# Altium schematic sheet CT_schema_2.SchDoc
size 362 x 192 mm
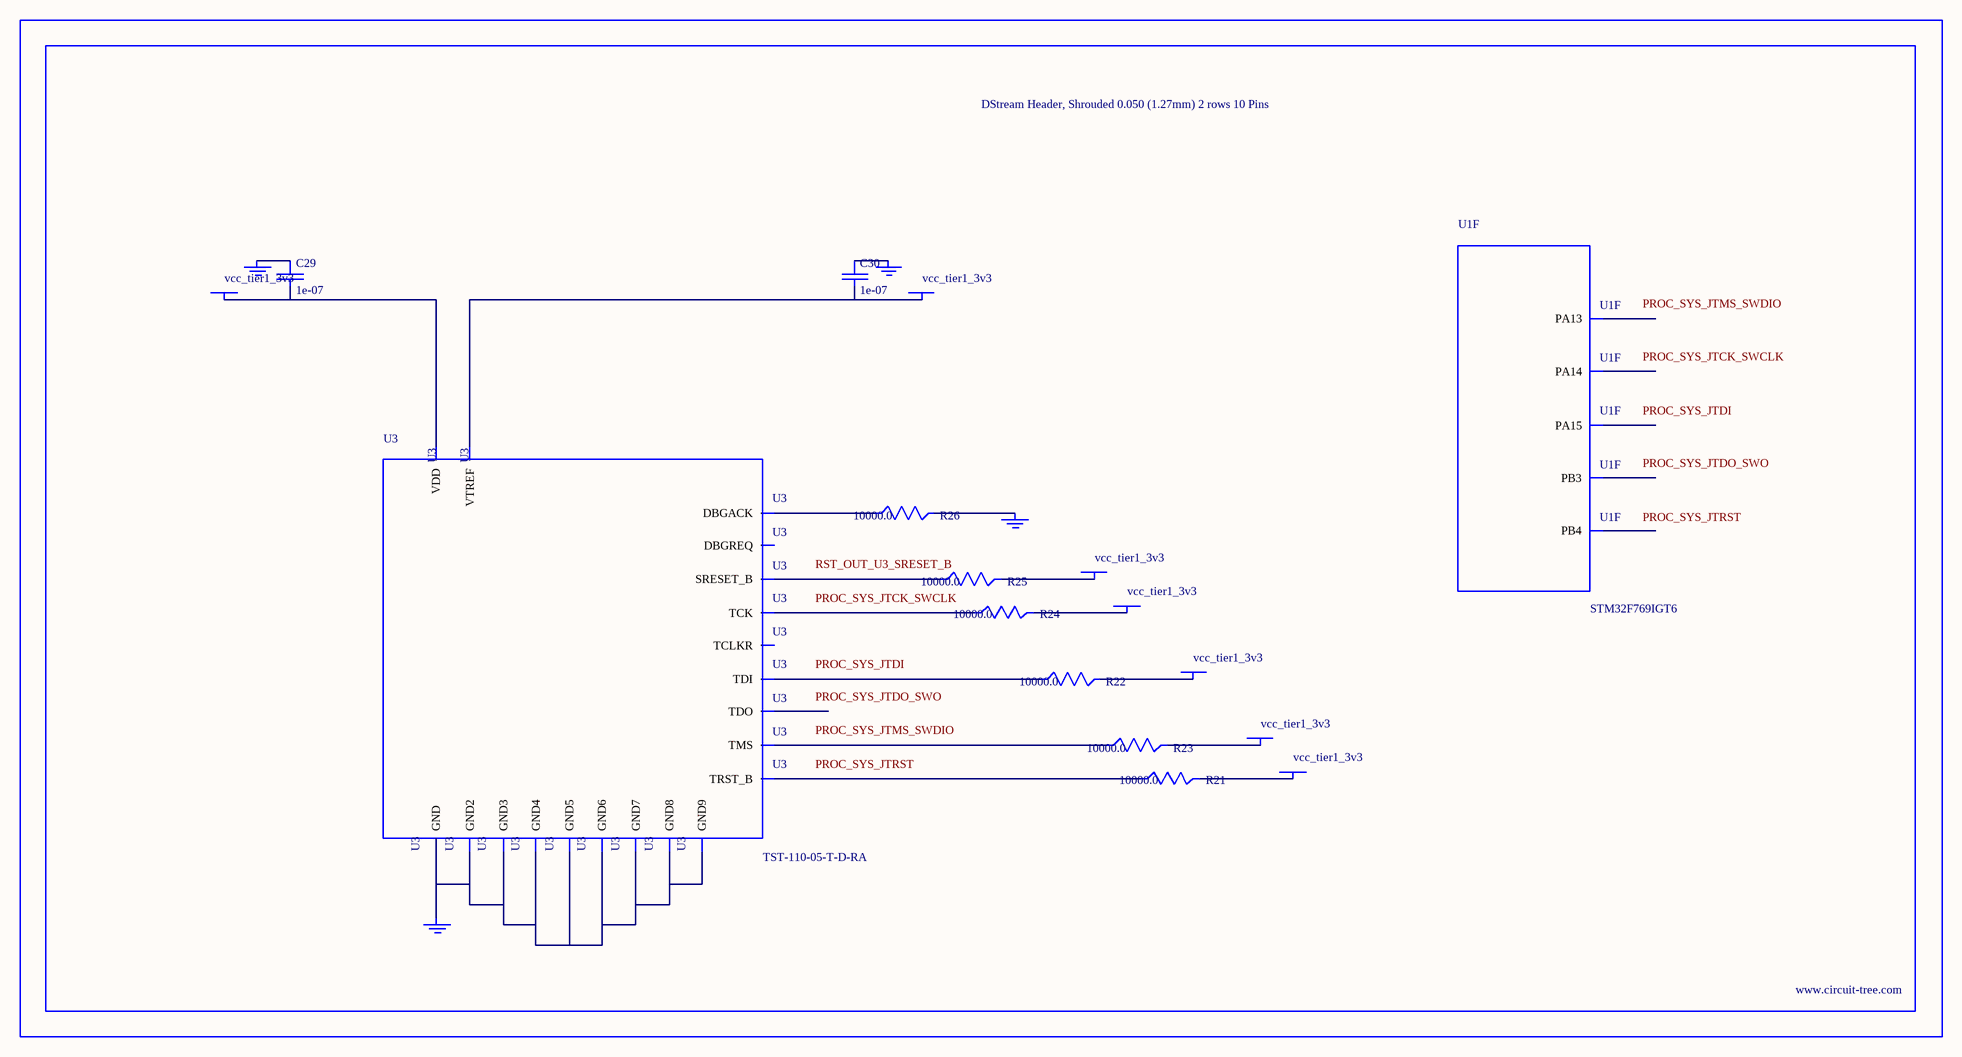
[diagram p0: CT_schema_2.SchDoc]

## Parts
BORDER1  (no value)
C29  1e-07  [C0402]
C30  1e-07  [C0402]
GND_INSTANCE_1_0  (no value)
GND_INSTANCE_1_1  (no value)
GND_INSTANCE_1_2  (no value)
GND_INSTANCE_1_3  (no value)
POWER_INSTANCE_1_0  vcc_tier1_3v3
POWER_INSTANCE_1_1  vcc_tier1_3v3
POWER_INSTANCE_1_2  vcc_tier1_3v3
POWER_INSTANCE_1_3  vcc_tier1_3v3
POWER_INSTANCE_1_4  vcc_tier1_3v3
POWER_INSTANCE_1_5  vcc_tier1_3v3
POWER_INSTANCE_1_6  vcc_tier1_3v3
R21  10000.0  [R0603]
R22  10000.0  [R0603]
R23  10000.0  [R0603]
R24  10000.0  [R0603]
R25  10000.0  [R0603]
R26  10000.0  [R0603]
U1  STM32F769IGT6  [LQFP176]  (part F of 13)
U3  TST-110-05-T-D-RA  [TST-110-05-T-D-RA]

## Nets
NetC29_1: C29.1 GND_INSTANCE_1_1.0(GND)
NetC29_2: C29.2 POWER_INSTANCE_1_1.0(PWR) U3.2(VDD)
NetC30_1: C30.1 GND_INSTANCE_1_0.0(GND)
NetC30_2: C30.2 POWER_INSTANCE_1_0.0(PWR) U3.1(VTREF)
NetGND_INSTANCE_1_2_0: GND_INSTANCE_1_2.0(GND) R26.2
NetGND_INSTANCE_1_3_0: GND_INSTANCE_1_3.0(GND) U3.4(GND) U3.6(GND2) U3.8(GND3) U3.10(GND4) U3.12(GND5) U3.14(GND6) U3.16(GND7) U3.18(GND8) U3.20(GND9)
NetPOWER_INSTANCE_1_2_0: POWER_INSTANCE_1_2.0(PWR) R21.2
NetPOWER_INSTANCE_1_3_0: POWER_INSTANCE_1_3.0(PWR) R22.2
NetPOWER_INSTANCE_1_4_0: POWER_INSTANCE_1_4.0(PWR) R23.2
NetPOWER_INSTANCE_1_5_0: POWER_INSTANCE_1_5.0(PWR) R24.2
NetPOWER_INSTANCE_1_6_0: POWER_INSTANCE_1_6.0(PWR) R25.2
NetR21_1: R21.1 U3.3(TRST_B)
NetR22_1: R22.1 U3.5(TDI)
NetR23_1: R23.1 U3.7(TMS)
NetR24_1: R24.1 U3.9(TCK)
NetR25_1: R25.1 U3.15(SRESET_B)
NetR26_1: R26.1 U3.19(DBGACK)

Not connected (* = marked no-connect by the designer): U1 128(PA13) 137(PA14) 138(PA15) 161(PB3) 162(PB4); U3 11(TCLKR) 13(TDO) 17(DBGREQ)

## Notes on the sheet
- Labels drawn without touching a wire or pin: PROC_SYS_JTCK_SWCLK, PROC_SYS_JTDI, PROC_SYS_JTDO_SWO, PROC_SYS_JTMS_SWDIO, PROC_SYS_JTRST, RST_OUT_U3_SRESET_B

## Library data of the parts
BORDER1 = BORDER_PAGE1
C29 C30 = C0402C104K3RACTU
GND_INSTANCE_1_0-GND_INSTANCE_1_3 = GND
POWER_INSTANCE_1_0-POWER_INSTANCE_1_6 = PWR
R21-R26 = RC0603JR-0710KL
